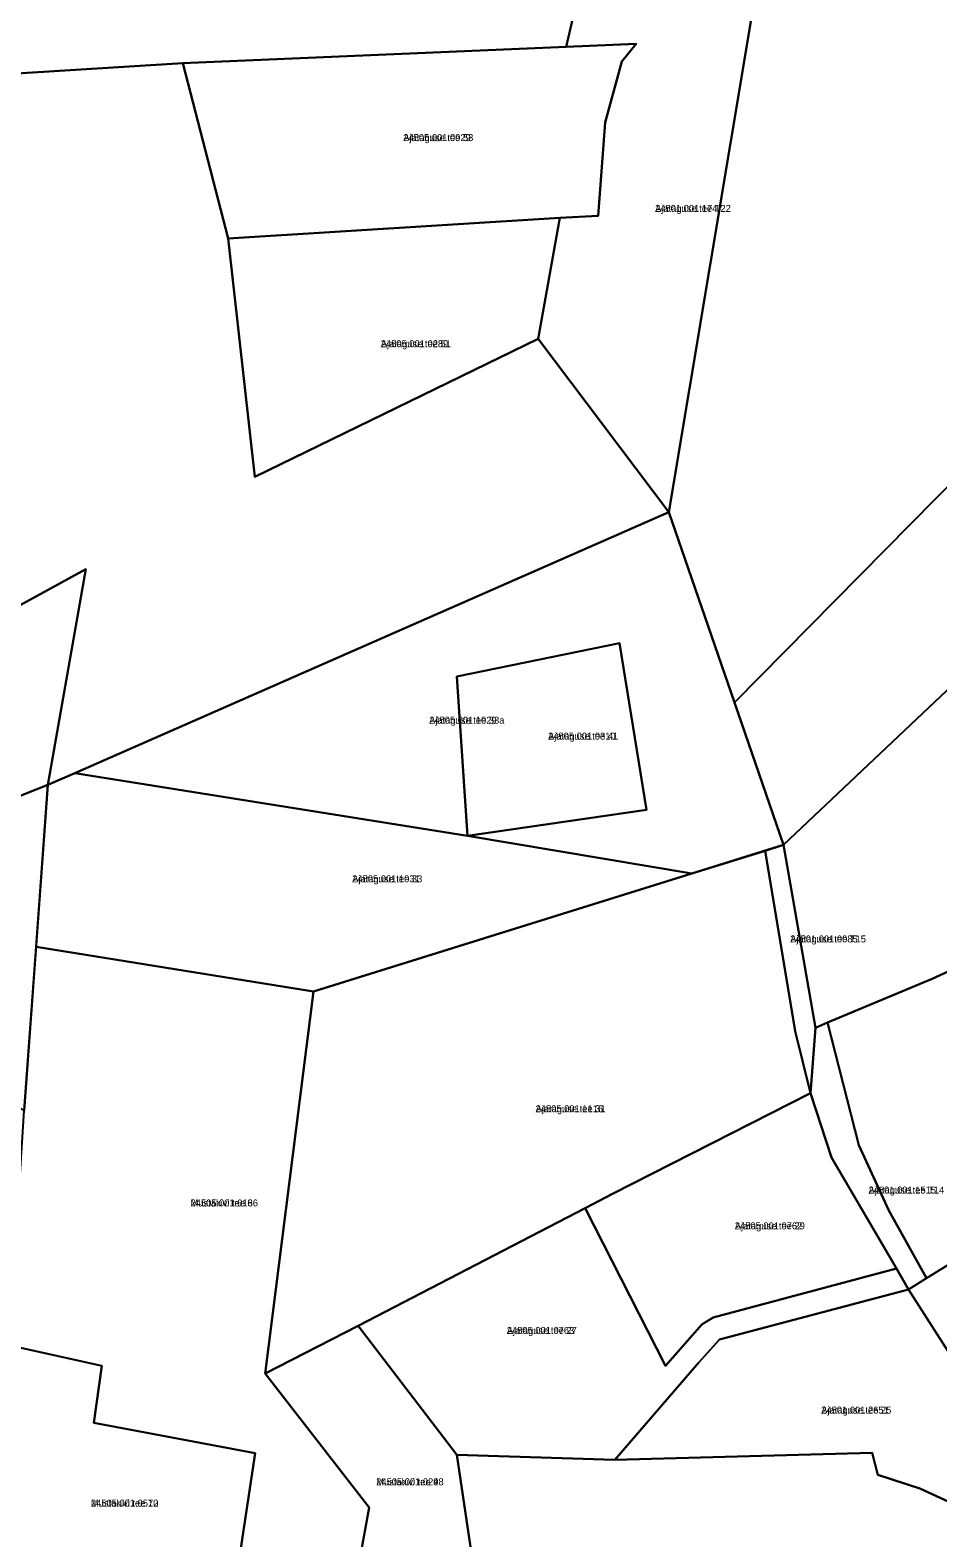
# Model space of a CAD drawing. Extents: x 551291 to 575799, y 6581704 to 6610137.
# Drawn here: x 565113.3 to 565308.4, y 6599774.9 to 6600099.1 of the extents above; entities that cross this region are included whole.
import ezdxf

# ---------------------------------------------------------------- set-up
doc = ezdxf.new("R2010")
doc.units = 0
for name, color, linetype in [('L_AADRESS', 7, 'Continuous'), ('PIIR', 7, 'Continuous'), ('TUNNUS', 7, 'Continuous')]:
    doc.layers.add(name, color=color, linetype=linetype)

msp = doc.modelspace()

# ---------------------------------------------------------------- linework, layer by layer
at = {"layer": 'PIIR'}
for points in [[(564967.21, 6600081.51), (564958.72, 6600110.95), (564939.93, 6600129.53), (564934.94, 6600148.67), (564932.63, 6600168.55), (564932.16, 6600190.5), (564934.49, 6600212.44), (564949.4, 6600207.8), (565154.07, 6600144.13), (565211.24, 6600124.38), (565233.33, 6600116.23), (565228.54, 6600095.57), (565146.06, 6600092), (565072.17, 6600087.45), (564985.2, 6600082.53)], [(565272.78, 6600128.51), (565250.61, 6599995.47), (565222.5, 6600032.72), (565227.15, 6600058.8), (565235.41, 6600059.18), (565236.9, 6600079.29), (565240.51, 6600092.36), (565243.6, 6600096.22), (565228.54, 6600095.57), (565233.33, 6600116.23)], [(565328.82, 6600115.2), (565339.19, 6600108.7), (565376.81, 6600078.85), (565404.72, 6600063.83), (565356.57, 6600047.64), (565264.68, 6599954.55), (565250.61, 6599995.47), (565272.78, 6600128.51)], [(565146.06, 6600092), (565228.54, 6600095.57), (565243.6, 6600096.22), (565240.51, 6600092.36), (565236.9, 6600079.29), (565235.41, 6600059.18), (565227.15, 6600058.8), (565155.85, 6600054.32)], [(565222.5, 6600032.72), (565161.58, 6600003.1), (565155.85, 6600054.32), (565227.15, 6600058.8)], [(565356.57, 6600047.64), (565374.91, 6600020.48), (565348.4, 6600003.1), (565358.44, 6599990.35), (565331.56, 6599968), (565327.2, 6599973.06), (565275.23, 6599923.89), (565264.68, 6599954.55)], [(565122.89, 6599939.34), (565250.61, 6599995.47), (565264.68, 6599954.55), (565275.23, 6599923.89), (565255.57, 6599917.76), (565207.32, 6599925.83)], [(565125.25, 6599983.2), (565117.1, 6599936.79), (565048.03, 6599909.27), (565047.9, 6599915.47), (565046.54, 6599978.55), (565095.33, 6599992.22), (565096.03, 6599967.19)], [(565357.15, 6599937.98), (565341.8, 6599916.41), (565335.7, 6599907.69), (565311.75, 6599897.15), (565307.23, 6599895.1), (565284.72, 6599885.68), (565282.1, 6599884.56), (565275.23, 6599923.89), (565327.2, 6599973.06), (565346.1, 6599951.04)], [(565245.8, 6599931.48), (565207.32, 6599925.83), (565205.01, 6599960.11), (565239.99, 6599967.29)], [(565205.01, 6599960.11), (565207.32, 6599925.83), (565245.8, 6599931.48), (565239.99, 6599967.29)], [(565117.1, 6599936.79), (565122.89, 6599939.34), (565207.32, 6599925.83), (565255.57, 6599917.76), (565174.17, 6599892.37), (565114.56, 6599901.99)], [(565117.1, 6599936.79), (565111.98, 6599866.77), (565048.26, 6599897.46), (565048.03, 6599909.27)], [(565174.17, 6599892.37), (565255.57, 6599917.76), (565271.27, 6599922.65), (565277.76, 6599883.87), (565281.06, 6599870.54), (565238.48, 6599848.84), (565232.62, 6599845.8), (565183.77, 6599820.48), (565163.82, 6599810.19)], [(565275.23, 6599923.89), (565282.1, 6599884.56), (565281.06, 6599870.54), (565277.76, 6599883.87), (565271.27, 6599922.65)], [(565111.98, 6599866.77), (565114.56, 6599901.99), (565174.17, 6599892.37), (565163.82, 6599810.19), (565186.16, 6599781.38), (565182.09, 6599758.87), (565158.49, 6599772.14), (565161.66, 6599793.06), (565126.96, 6599799.58), (565128.69, 6599811.88), (565109.34, 6599816.16), (565110.65, 6599845.2)], [(565307.23, 6599895.1), (565311.75, 6599897.15), (565317.57, 6599889.12), (565318.84, 6599888.16), (565323.42, 6599880.64), (565322.06, 6599871.22), (565333.1, 6599847.36), (565305.99, 6599830.7), (565297.92, 6599845.26), (565291.42, 6599859.34), (565284.72, 6599885.68)], [(565282.1, 6599884.56), (565284.72, 6599885.68), (565291.42, 6599859.34), (565297.92, 6599845.26), (565305.99, 6599830.7), (565302.14, 6599828.27), (565299.52, 6599832.83), (565285.58, 6599856.66), (565281.06, 6599870.54)], [(565281.06, 6599870.54), (565285.58, 6599856.66), (565299.52, 6599832.83), (565260.12, 6599822.3), (565257.65, 6599820.76), (565249.88, 6599811.9), (565232.62, 6599845.8), (565238.48, 6599848.84)], [(565302.14, 6599828.27), (565305.99, 6599830.7), (565333.1, 6599847.36), (565348.04, 6599827.75), (565315.76, 6599806.97)], [(565299.52, 6599832.83), (565302.14, 6599828.27), (565261.5, 6599817.5), (565256.99, 6599812.48), (565238.96, 6599791.68), (565205.04, 6599792.71), (565183.77, 6599820.48), (565232.62, 6599845.8), (565249.88, 6599811.9), (565257.65, 6599820.76), (565260.12, 6599822.3)], [(565261.5, 6599817.5), (565302.14, 6599828.27), (565315.76, 6599806.97), (565329.34, 6599785.62), (565335.34, 6599776.15), (565331.94, 6599774.94), (565324.54, 6599776.31), (565304.56, 6599785.51), (565295.55, 6599788.43), (565294.32, 6599793.15), (565238.96, 6599791.68), (565256.99, 6599812.48)], [(565182.09, 6599758.87), (565186.16, 6599781.38), (565163.82, 6599810.19), (565183.77, 6599820.48), (565205.04, 6599792.71), (565211.52, 6599748.88)], [(565109.34, 6599816.16), (565128.69, 6599811.88), (565126.96, 6599799.58), (565161.66, 6599793.06), (565158.49, 6599772.14), (565156.63, 6599759.41), (565154.82, 6599746.75), (565091.03, 6599755.84), (565103.89, 6599778.02), (565107.81, 6599805.46)], [(565211.52, 6599748.88), (565205.04, 6599792.71), (565238.96, 6599791.68), (565294.32, 6599793.15), (565295.55, 6599788.43), (565304.56, 6599785.51), (565324.54, 6599776.31), (565331.94, 6599774.94), (565335.34, 6599776.15), (565341.59, 6599763.64), (565212.78, 6599739.77)]]:
    msp.add_lwpolyline(points, close=True, dxfattribs=at)
msp.add_lwpolyline([(565072.17, 6600087.45), (565146.06, 6600092), (565155.85, 6600054.32), (565161.58, 6600003.1), (565222.5, 6600032.72), (565250.61, 6599995.47), (565122.89, 6599939.34), (565117.1, 6599936.79), (565125.25, 6599983.2), (565096.03, 6599967.19)], dxfattribs=at)

# ---------------------------------------------------------------- texts
at = {"layer": 'L_AADRESS'}
for s, p in [('Ajataguse tee 53', (565193.5, 6600075.27)), ('Ajataguse tee T22', (565247.64, 6600060.05)), ('Ajataguse tee 51', (565188.66, 6600030.95)), ('Ajataguse tee 33a', (565199.06, 6599949.98)), ('Ajataguse tee 41', (565224.64, 6599946.56)), ('Ajataguse tee 33', (565182.52, 6599915.86)), ('Ajataguse tee T15', (565276.69, 6599902.93)), ('Ajataguse tee 31', (565221.94, 6599866.42)), ('Ajataguse tee T14', (565293.53, 6599848.93)), ('Mustakivi tee 6', (565147.75, 6599846.15)), ('Ajataguse tee 29', (565264.78, 6599841.22)), ('Ajataguse tee 27', (565215.75, 6599818.74)), ('Ajataguse tee 25', (565283.37, 6599801.61)), ('Mustakivi tee 4', (565187.67, 6599786.18)), ('Mustakivi tee 10', (565126.34, 6599781.6))]:
    msp.add_text(s, height=1.5, dxfattribs=at).set_placement(p)
at = {"layer": 'TUNNUS'}
for s, p in [('24505:001:0929', (565193.5, 6600075.27)), ('24501:001:1747', (565247.64, 6600060.05)), ('24505:001:0289', (565188.66, 6600030.95)), ('24505:001:1029', (565199.06, 6599949.98)), ('24505:001:0310', (565224.64, 6599946.56)), ('24505:001:1031', (565182.52, 6599915.86)), ('24501:001:0085', (565276.69, 6599902.93)), ('24505:001:1116', (565221.94, 6599866.42)), ('24501:001:1515', (565293.53, 6599848.93)), ('24505:001:0136', (565147.75, 6599846.15)), ('24505:001:0762', (565264.78, 6599841.22)), ('24505:001:0763', (565215.75, 6599818.74)), ('24501:001:2651', (565283.37, 6599801.61)), ('24505:001:0298', (565187.67, 6599786.18)), ('24505:001:0572', (565126.34, 6599781.6))]:
    msp.add_text(s, height=1.5, dxfattribs=at).set_placement(p)

doc.saveas('drawing.dxf')
